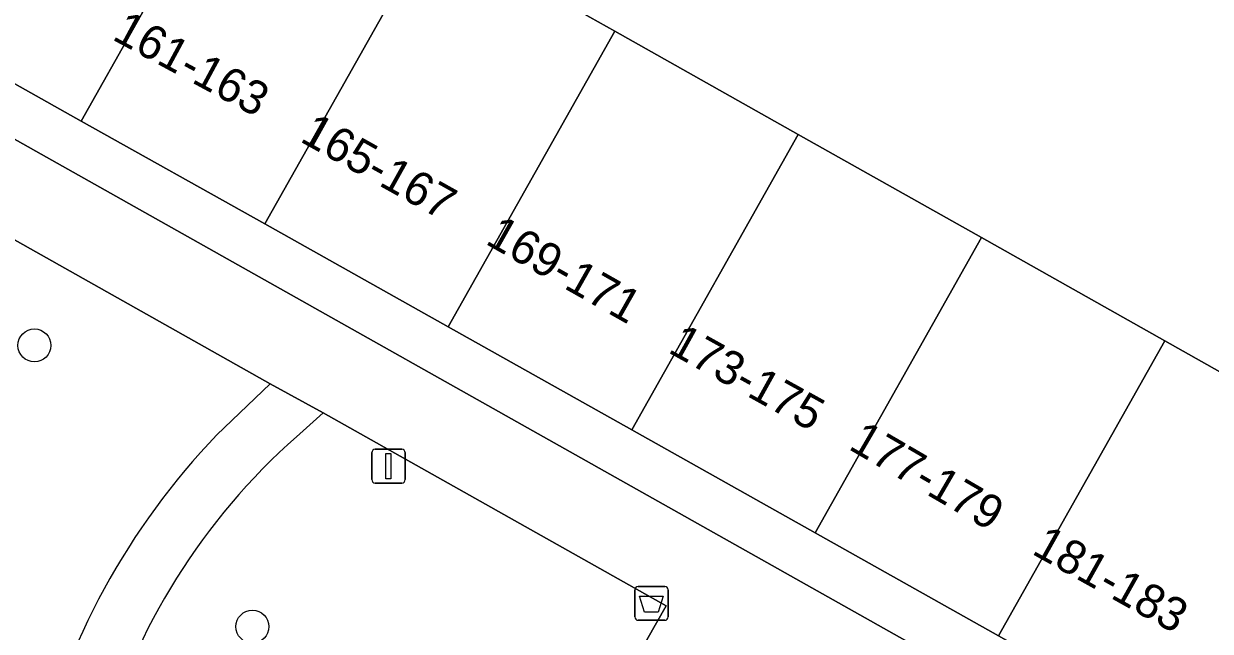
# Model space of a CAD drawing. Extents: x 159279 to 160377, y 384531 to 385888.
# Drawn here: x 159673.98 to 159709.16, y 384917.67 to 384935.7 of the extents above; entities that cross this region are included whole.
import ezdxf

# ---------------------------------------------------------------- set-up
doc = ezdxf.new("R2010")
doc.units = 0
for name, color, linetype in [('IMGEO_Afvalbak', 7, 'Continuous'), ('IMGEO_Boom', 7, 'Continuous'), ('IMGEO_Erf', 7, 'Continuous'), ('IMGEO_Groenvoorziening', 7, 'Continuous'), ('IMGEO_Lichtmast', 7, 'Continuous'), ('IMGEO_Pand', 7, 'Continuous'), ('IMGEO_Pand_nummerreeks', 7, 'Continuous'), ('IMGEO_Voetpad_open', 7, 'Continuous')]:
    doc.layers.add(name, color=color, linetype=linetype)

msp = doc.modelspace()

# ---------------------------------------------------------------- linework, layer by layer
at = {"layer": 'IMGEO_Afvalbak'}
for p, q in [((159692.098, 384918.1), (159692.098, 384918.9)), ((159692.098, 384918.9), (159692.098, 384918.1)), ((159692.198, 384919), (159692.988, 384919)), ((159692.988, 384919), (159692.198, 384919)), ((159693.088, 384918.9), (159693.088, 384918.1)), ((159693.088, 384918.1), (159693.088, 384918.9)), ((159692.988, 384918), (159692.198, 384918)), ((159692.198, 384918), (159692.988, 384918))]:
    msp.add_line(p, q, dxfattribs=at)
msp.add_lwpolyline([(159692.241, 384918.714), (159692.945, 384918.714), (159692.796, 384918.244), (159692.39, 384918.244), (159692.241, 384918.714)], dxfattribs=at)
for centre, start, end in [((159692.198, 384918.9), 90, 180), ((159692.198, 384918.9), 90, 180), ((159692.988, 384918.9), 0, 90), ((159692.988, 384918.9), 360, 90), ((159692.198, 384918.1), 180, 270), ((159692.198, 384918.1), 180, 270), ((159692.988, 384918.1), 270, 0), ((159692.988, 384918.1), 270, 0)]:
    msp.add_arc(centre, 0.1, start, end, dxfattribs=at)
at = {"layer": 'IMGEO_Boom'}
for centre in [(159674.302, 384926.155), (159680.762, 384917.811)]:
    msp.add_circle(centre, 0.489, dxfattribs=at)
at = {"layer": 'IMGEO_Erf'}
msp.add_lwpolyline([(159643.607, 384964.181), (159647.503, 384959.44), (159651.4, 384954.699), (159649.084, 384952.791), (159652.211, 384950.895), (159656.129, 384948.52), (159658.903, 384953.838), (159664.337, 384950.777), (159669.772, 384947.716), (159675.206, 384944.655), (159680.641, 384941.594), (159686.075, 384938.533), (159691.51, 384935.472), (159696.944, 384932.411), (159702.378, 384929.35), (159707.813, 384926.289), (159713.247, 384923.228), (159718.682, 384920.167), (159724.116, 384917.106), (159724.215, 384917.05), (159725.856, 384920.3), (159727.342, 384919.461), (159731.696, 384917.004), (159730.233, 384914.369)], dxfattribs=at)
at = {"layer": 'IMGEO_Groenvoorziening'}
for points in [[(159679.712, 384923.502), (159681.286, 384925.015), (159672.225, 384930.114), (159670.604, 384929.208)], [(159692.459, 384917.419), (159693.028, 384918.426), (159682.858, 384924.153), (159682.067, 384923.446)]]:
    msp.add_lwpolyline(points, dxfattribs=at)
for centre, radius, start, end in [((159695.308, 384908.583), 21.583, 136.271, 166.4054), ((159694.985, 384908.916), 19.442, 131.637, 164.1671)]:
    msp.add_arc(centre, radius, start, end, dxfattribs=at)
at = {"layer": 'IMGEO_Lichtmast'}
for p, q in [((159684.402, 384923.072), (159685.192, 384923.072)), ((159685.192, 384923.072), (159684.402, 384923.072)), ((159684.302, 384922.172), (159684.302, 384922.972)), ((159684.302, 384922.972), (159684.302, 384922.172)), ((159685.292, 384922.972), (159685.292, 384922.172)), ((159685.292, 384922.172), (159685.292, 384922.972)), ((159685.192, 384922.072), (159684.402, 384922.072)), ((159684.402, 384922.072), (159685.192, 384922.072))]:
    msp.add_line(p, q, dxfattribs=at)
msp.add_lwpolyline([(159684.722, 384922.947), (159684.872, 384922.947), (159684.872, 384922.197), (159684.722, 384922.197), (159684.722, 384922.947)], dxfattribs=at)
for centre, start, end in [((159684.402, 384922.972), 90, 180), ((159684.402, 384922.972), 90, 180), ((159685.192, 384922.972), 0, 90), ((159685.192, 384922.972), 360, 90), ((159684.402, 384922.172), 180, 270), ((159684.402, 384922.172), 180, 270), ((159685.192, 384922.172), 270, 0), ((159685.192, 384922.172), 270, 0)]:
    msp.add_arc(centre, 0.1, start, end, dxfattribs=at)
at = {"layer": 'IMGEO_Pand'}
for points in [[(159675.692, 384932.809), (159680.641, 384941.594), (159675.206, 384944.655), (159670.254, 384935.863)], [(159681.131, 384929.755), (159686.075, 384938.533), (159680.641, 384941.594), (159675.692, 384932.809)], [(159686.569, 384926.7), (159691.51, 384935.472), (159686.075, 384938.533), (159681.131, 384929.755)], [(159692.007, 384923.646), (159696.944, 384932.411), (159691.51, 384935.472), (159686.569, 384926.7)], [(159697.445, 384920.592), (159702.378, 384929.35), (159696.944, 384932.411), (159692.007, 384923.646)], [(159702.884, 384917.538), (159707.813, 384926.289), (159702.378, 384929.35), (159697.445, 384920.592)], [(159708.322, 384914.484), (159713.247, 384923.228), (159707.813, 384926.289), (159702.884, 384917.538)]]:
    msp.add_lwpolyline(points, close=True, dxfattribs=at)
at = {"layer": 'IMGEO_Voetpad_open'}
msp.add_lwpolyline([(159686.569, 384926.7), (159681.131, 384929.755), (159675.692, 384932.809), (159670.254, 384935.863), (159664.816, 384938.917), (159659.377, 384941.971), (159654.078, 384944.948), (159653.389, 384943.716), (159717.281, 384907.744), (159718.765, 384906.908), (159719.473, 384908.221), (159713.76, 384911.429), (159708.322, 384914.484), (159702.884, 384917.538), (159697.445, 384920.592), (159692.007, 384923.646)], close=True, dxfattribs=at)
for points in [[(159646.672, 384944.473), (159670.481, 384931.091), (159672.225, 384930.114), (159681.286, 384925.015), (159682.858, 384924.153), (159693.028, 384918.426), (159692.459, 384917.419), (159691.878, 384916.391)], [(159714.732, 384903.749), (159717.281, 384907.744), (159653.389, 384943.716)], [(159682.067, 384923.446), (159682.858, 384924.153), (159681.286, 384925.015), (159679.712, 384923.502)]]:
    msp.add_lwpolyline(points, dxfattribs=at)
for centre, radius, start, end in [((159695.308, 384908.583), 21.583, 136.271, 166.4054), ((159694.985, 384908.916), 19.442, 131.637, 164.1671)]:
    msp.add_arc(centre, radius, start, end, dxfattribs=at)

# ---------------------------------------------------------------- texts
at = {"layer": 'IMGEO_Pand_nummerreeks'}
for s, rotation, p in [('161-163', 331.6157, (159676.573, 384935.243)), ('165-167', 330.8651, (159682.14, 384932.219)), ('169-171', 330.5099, (159687.636, 384929.183)), ('173-175', 331.0255, (159693.051, 384925.963)), ('177-179', 329.7994, (159698.4, 384923.095)), ('181-183', 330.7505, (159703.835, 384919.988))]:
    msp.add_text(s, height=1, rotation=rotation, dxfattribs=at).set_placement(p)

doc.saveas('drawing.dxf')
